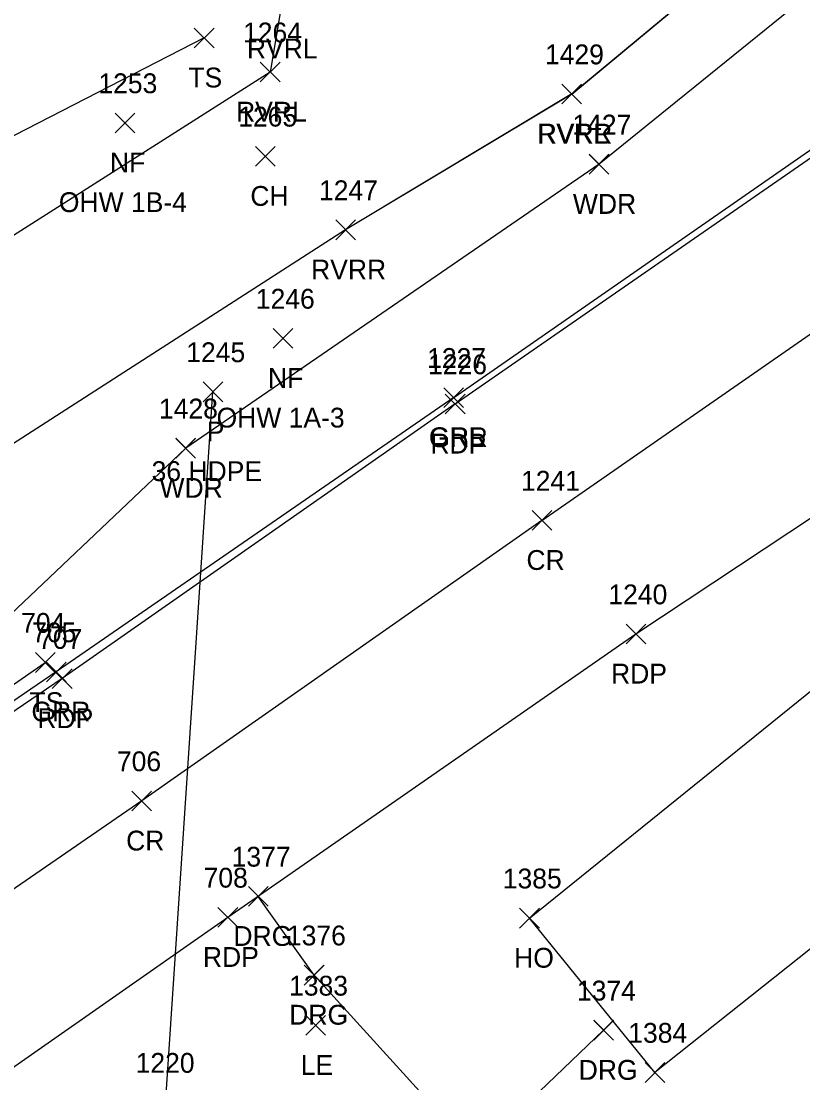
# Model space of a CAD drawing. Extents: x 1528286 to 1556263, y 492387 to 508952.
# Drawn here: x 1528937.9 to 1529016.8, y 492961.3 to 493068.5 of the extents above; entities that cross this region are included whole.
import ezdxf

# ---------------------------------------------------------------- set-up
doc = ezdxf.new("R2010")
doc.units = 0
for name, color, linetype in [('D_A', 7, 'Continuous'), ('D_C', 7, 'Continuous'), ('D_I', 7, 'Continuous'), ('D_TIC', 7, 'Continuous'), ('DCP', 7, 'Continuous'), ('L_A', 7, 'Continuous'), ('L_C', 7, 'Continuous'), ('L_I', 7, 'Continuous'), ('L_TIC', 7, 'Continuous'), ('LAWA', 7, 'Continuous'), ('LAWE', 7, 'Continuous'), ('LBC', 7, 'Continuous'), ('LELB', 7, 'Continuous'), ('P_A', 7, 'Continuous'), ('P_I', 7, 'Continuous'), ('P_TIC', 7, 'Continuous'), ('PET', 7, 'Continuous'), ('PRC', 7, 'Continuous'), ('R_A', 7, 'Continuous'), ('R_I', 7, 'Continuous'), ('R_TIC', 7, 'Continuous'), ('RDG', 7, 'Continuous'), ('RGR', 7, 'Continuous')]:
    doc.layers.add(name, color=color, linetype=linetype)

msp = doc.modelspace()

# ---------------------------------------------------------------- linework, layer by layer
at = {"layer": 'D_TIC'}
for points in [[(1528956.21, 493030.06), (1528958.21, 493032.06)], [(1528958.21, 493030.06), (1528956.21, 493032.06)], [(1528956.21, 493030.06), (1528958.21, 493032.06)], [(1528958.21, 493030.06), (1528956.21, 493032.06)]]:
    msp.add_lwpolyline(points, dxfattribs=at)
at = {"layer": 'DCP'}
msp.add_lwpolyline([(1528951.98, 492952.57), (1528957.21, 493031.06)], dxfattribs=at)
msp.add_lwpolyline([(1528951.98, 492952.57), (1528957.21, 493031.06)], dxfattribs=at)
at = {"layer": 'L_TIC'}
for points in [[(1528955.32, 493065.79), (1528957.32, 493067.79)], [(1528957.32, 493065.79), (1528955.32, 493067.79)], [(1528955.32, 493065.79), (1528957.32, 493067.79)], [(1528957.32, 493065.79), (1528955.32, 493067.79)], [(1528961.99, 493062.34), (1528963.99, 493064.34)], [(1528963.99, 493062.34), (1528961.99, 493064.34)], [(1528961.99, 493062.34), (1528963.99, 493064.34)], [(1528963.99, 493062.34), (1528961.99, 493064.34)], [(1528992.43, 493060.13), (1528994.43, 493062.13)], [(1528994.43, 493060.13), (1528992.43, 493062.13)], [(1528992.43, 493060.13), (1528994.43, 493062.13)], [(1528994.43, 493060.13), (1528992.43, 493062.13)], [(1528992.43, 493060.12), (1528994.43, 493062.12)], [(1528994.43, 493060.12), (1528992.43, 493062.12)], [(1528992.43, 493060.12), (1528994.43, 493062.12)], [(1528994.43, 493060.12), (1528992.43, 493062.12)], [(1528947.34, 493057.21), (1528949.34, 493059.21)], [(1528949.34, 493057.21), (1528947.34, 493059.21)], [(1528947.34, 493057.21), (1528949.34, 493059.21)], [(1528949.34, 493057.21), (1528947.34, 493059.21)], [(1528961.5, 493053.84), (1528963.5, 493055.84)], [(1528963.5, 493053.84), (1528961.5, 493055.84)], [(1528961.5, 493053.84), (1528963.5, 493055.84)], [(1528963.5, 493053.84), (1528961.5, 493055.84)], [(1528995.19, 493053.04), (1528997.19, 493055.04)], [(1528997.19, 493053.04), (1528995.19, 493055.04)], [(1528995.19, 493053.03), (1528997.19, 493055.03)], [(1528997.19, 493053.03), (1528995.19, 493055.03)], [(1528969.61, 493046.41), (1528971.61, 493048.41)], [(1528971.61, 493046.41), (1528969.61, 493048.41)], [(1528969.61, 493046.41), (1528971.61, 493048.41)], [(1528971.61, 493046.41), (1528969.61, 493048.41)], [(1528963.29, 493035.46), (1528965.29, 493037.46)], [(1528965.29, 493035.46), (1528963.29, 493037.46)], [(1528963.29, 493035.46), (1528965.29, 493037.46)], [(1528965.29, 493035.46), (1528963.29, 493037.46)], [(1528953.46, 493024.38), (1528955.46, 493026.38)], [(1528955.46, 493024.38), (1528953.46, 493026.38)], [(1528953.46, 493024.37), (1528955.46, 493026.37)], [(1528955.46, 493024.37), (1528953.46, 493026.37)], [(1528939.29, 493002.74), (1528941.29, 493004.74)], [(1528941.29, 493002.74), (1528939.29, 493004.74)], [(1528939.29, 493002.74), (1528941.29, 493004.74)], [(1528941.29, 493002.74), (1528939.29, 493004.74)], [(1528988.17, 492976.94), (1528990.17, 492978.94)], [(1528990.17, 492976.94), (1528988.17, 492978.94)], [(1528988.17, 492976.94), (1528990.17, 492978.94)], [(1528990.17, 492976.94), (1528988.17, 492978.94)], [(1528966.59, 492966.12), (1528968.59, 492968.12)], [(1528968.59, 492966.12), (1528966.59, 492968.12)], [(1528966.59, 492966.12), (1528968.59, 492968.12)], [(1528968.59, 492966.12), (1528966.59, 492968.12)], [(1529000.83, 492961.36), (1529002.83, 492963.36)], [(1529002.83, 492961.36), (1529000.83, 492963.36)], [(1529000.83, 492961.36), (1529002.83, 492963.36)], [(1529002.83, 492961.36), (1529000.83, 492963.36)]]:
    msp.add_lwpolyline(points, dxfattribs=at)
at = {"layer": 'LAWA'}
for points in [[(1529161.79, 493169.98), (1529145.79, 493161.64), (1529103.54, 493137.09), (1529078.89, 493120.12), (1529036.96, 493087.03), (1528996.19, 493054.04), (1528954.46, 493025.37)], [(1529161.79, 493169.98), (1529145.79, 493161.64), (1529103.54, 493137.09), (1529078.89, 493120.12), (1529036.96, 493087.03), (1528996.19, 493054.03), (1528954.46, 493025.38)], [(1528954.46, 493025.38), (1528932.82, 493004.86)], [(1528954.46, 493025.37), (1528932.82, 493004.86)]]:
    msp.add_lwpolyline(points, dxfattribs=at)
at = {"layer": 'LAWE'}
for points in [[(1528993.43, 493061.12), (1529028.67, 493090.37), (1529051.82, 493126.54), (1529095.12, 493164.29)], [(1528993.43, 493061.13), (1529028.67, 493090.37), (1529051.83, 493126.54), (1529095.12, 493164.29)], [(1528964.08, 493069.72), (1528962.99, 493063.34)], [(1528964.07, 493069.72), (1528962.99, 493063.34)], [(1528962.99, 493063.34), (1528890.67, 493017.33), (1528875.74, 493008.39), (1528841.38, 492996.85), (1528822.77, 492990.39)], [(1528962.99, 493063.34), (1528890.67, 493017.33), (1528875.74, 493008.39), (1528841.38, 492996.85), (1528822.77, 492990.39)], [(1528993.43, 493061.13), (1528970.61, 493047.41)], [(1528993.43, 493061.12), (1528970.61, 493047.41)], [(1528970.61, 493047.41), (1528902.86, 493003.86), (1528888.6, 492991.51), (1528860.16, 492972.68)], [(1528970.61, 493047.41), (1528902.86, 493003.86), (1528888.6, 492991.51), (1528860.16, 492972.68)]]:
    msp.add_lwpolyline(points, dxfattribs=at)
at = {"layer": 'LBC'}
msp.add_lwpolyline([(1529001.83, 492962.36), (1528989.17, 492977.94), (1529034.67, 493014.69), (1529047.99, 492999.03), (1529001.83, 492962.36)], dxfattribs=at)
msp.add_lwpolyline([(1529001.83, 492962.36), (1528989.17, 492977.94), (1529034.67, 493014.69), (1529047.99, 492999.03), (1529001.83, 492962.36)], dxfattribs=at)
at = {"layer": 'LELB'}
for points in [[(1528956.32, 493066.79), (1528901.19, 493038.46), (1528892.87, 493033.69), (1528869.88, 493022.89)], [(1528956.32, 493066.79), (1528901.19, 493038.46), (1528892.87, 493033.69), (1528869.88, 493022.89)], [(1528511.53, 492702.85), (1528534.14, 492721.31), (1528572.64, 492751.16), (1528586.73, 492763.59), (1528600.5, 492766.35), (1528613.46, 492775.52), (1528652.2, 492802.53), (1528688.62, 492828.26), (1528710.29, 492843.12), (1528742.91, 492866.47), (1528778.71, 492891.27), (1528817.45, 492919.08), (1528857.75, 492946.94), (1528897.37, 492973.98), (1528940.29, 493003.74)], [(1528511.53, 492702.85), (1528534.14, 492721.31), (1528572.64, 492751.16), (1528586.73, 492763.59), (1528600.5, 492766.35), (1528613.46, 492775.52), (1528652.2, 492802.53), (1528688.62, 492828.26), (1528710.29, 492843.12), (1528742.91, 492866.47), (1528778.71, 492891.27), (1528817.45, 492919.08), (1528857.75, 492946.94), (1528897.37, 492973.98), (1528940.29, 493003.74)]]:
    msp.add_lwpolyline(points, dxfattribs=at)
at = {"layer": 'P_TIC'}
for points in [[(1528980.67, 493028.84), (1528982.67, 493030.84)], [(1528982.67, 493028.84), (1528980.67, 493030.84)], [(1528980.67, 493028.84), (1528982.67, 493030.84)], [(1528982.67, 493028.84), (1528980.67, 493030.84)], [(1528989.43, 493017.09), (1528991.43, 493019.09)], [(1528991.43, 493017.09), (1528989.43, 493019.09)], [(1528989.43, 493017.09), (1528991.43, 493019.09)], [(1528991.43, 493017.09), (1528989.43, 493019.09)], [(1528998.91, 493005.62), (1529000.91, 493007.62)], [(1529000.91, 493005.62), (1528998.91, 493007.62)], [(1528998.91, 493005.62), (1529000.91, 493007.62)], [(1529000.91, 493005.62), (1528998.91, 493007.62)], [(1528941, 493001.12), (1528943, 493003.12)], [(1528943, 493001.12), (1528941, 493003.12)], [(1528941, 493001.12), (1528943, 493003.12)], [(1528943, 493001.12), (1528941, 493003.12)], [(1528949.02, 492988.77), (1528951.02, 492990.77)], [(1528951.02, 492988.77), (1528949.02, 492990.77)], [(1528949.02, 492988.77), (1528951.02, 492990.77)], [(1528951.02, 492988.77), (1528949.02, 492990.77)], [(1528957.71, 492977.02), (1528959.71, 492979.02)], [(1528959.71, 492977.02), (1528957.71, 492979.02)], [(1528957.71, 492977.02), (1528959.71, 492979.02)], [(1528959.71, 492977.02), (1528957.71, 492979.02)]]:
    msp.add_lwpolyline(points, dxfattribs=at)
at = {"layer": 'PET'}
for points in [[(1528981.67, 493029.84), (1529023.32, 493058.68), (1529062.76, 493086.59), (1529101.46, 493113.53), (1529137.06, 493138.01), (1529145.3, 493125.26), (1529153.7, 493113.65), (1529119.46, 493089.42), (1529079.43, 493062), (1529041.27, 493034), (1528999.91, 493006.62)], [(1528981.67, 493029.84), (1529023.32, 493058.68), (1529062.76, 493086.59), (1529101.46, 493113.53), (1529137.06, 493138.01), (1529145.3, 493125.26), (1529153.7, 493113.65), (1529119.46, 493089.42), (1529079.43, 493062), (1529041.27, 493034), (1528999.91, 493006.62)], [(1528981.67, 493029.84), (1528942, 493002.12)], [(1528981.67, 493029.84), (1528942, 493002.12)], [(1528999.91, 493006.62), (1528958.71, 492978.02)], [(1528999.91, 493006.62), (1528958.71, 492978.02)], [(1528942, 493002.12), (1528898.48, 492972.51), (1528859.28, 492945.34), (1528819.08, 492917.53), (1528787.55, 492894.48), (1528780.46, 492889.94), (1528744.23, 492865.12), (1528711.17, 492841.82), (1528689.56, 492826.66), (1528653.33, 492801.52)], [(1528942, 493002.12), (1528898.48, 492972.51), (1528859.28, 492945.34), (1528819.08, 492917.53), (1528787.55, 492894.48), (1528780.46, 492889.94), (1528744.23, 492865.12), (1528711.17, 492841.82), (1528689.56, 492826.66), (1528653.33, 492801.52)], [(1528958.71, 492978.02), (1528915.24, 492947.63), (1528876.05, 492920.66), (1528835.6, 492893.02)], [(1528958.71, 492978.02), (1528915.24, 492947.63), (1528876.05, 492920.66), (1528835.6, 492893.02)]]:
    msp.add_lwpolyline(points, dxfattribs=at)
at = {"layer": 'PRC'}
for points in [[(1528990.43, 493018.09), (1529032.37, 493047.2), (1529072.04, 493074.3), (1529110.99, 493101.46)], [(1528990.43, 493018.09), (1529032.37, 493047.2), (1529072.04, 493074.3), (1529110.99, 493101.46)], [(1528990.43, 493018.09), (1528950.02, 492989.77)], [(1528990.43, 493018.09), (1528950.02, 492989.77)], [(1528950.02, 492989.77), (1528907.21, 492960.29), (1528867.74, 492932.71), (1528827.79, 492905.43)], [(1528950.02, 492989.77), (1528907.21, 492960.29), (1528867.74, 492932.71), (1528827.79, 492905.43)]]:
    msp.add_lwpolyline(points, dxfattribs=at)
at = {"layer": 'R_TIC'}
for points in [[(1528980.52, 493029.48), (1528982.52, 493031.48)], [(1528982.52, 493029.48), (1528980.52, 493031.48)], [(1528980.52, 493029.48), (1528982.52, 493031.48)], [(1528982.52, 493029.48), (1528980.52, 493031.48)], [(1528980.52, 493029.48), (1528982.52, 493031.48)], [(1528982.52, 493029.48), (1528980.52, 493031.48)], [(1528980.52, 493029.48), (1528982.52, 493031.48)], [(1528982.52, 493029.48), (1528980.52, 493031.48)], [(1528940.4, 493001.79), (1528942.4, 493003.79)], [(1528942.4, 493001.79), (1528940.4, 493003.79)], [(1528940.4, 493001.79), (1528942.4, 493003.79)], [(1528942.4, 493001.79), (1528940.4, 493003.79)], [(1528960.79, 492979.14), (1528962.79, 492981.14)], [(1528962.79, 492979.14), (1528960.79, 492981.14)], [(1528960.79, 492979.14), (1528962.79, 492981.14)], [(1528962.79, 492979.14), (1528960.79, 492981.14)], [(1528966.42, 492971.19), (1528968.42, 492973.19)], [(1528968.42, 492971.19), (1528966.42, 492973.19)], [(1528966.43, 492971.19), (1528968.43, 492973.19)], [(1528968.43, 492971.19), (1528966.43, 492973.19)], [(1528995.65, 492965.63), (1528997.65, 492967.63)], [(1528997.65, 492965.63), (1528995.65, 492967.63)], [(1528995.65, 492965.62), (1528997.65, 492967.62)], [(1528997.65, 492965.62), (1528995.65, 492967.62)]]:
    msp.add_lwpolyline(points, dxfattribs=at)
at = {"layer": 'RDG'}
for points in [[(1528996.65, 492966.62), (1528983.73, 492954.24), (1528967.43, 492972.19), (1528961.79, 492980.14)], [(1528996.65, 492966.63), (1528983.73, 492954.25), (1528967.42, 492972.19), (1528961.79, 492980.14)]]:
    msp.add_lwpolyline(points, dxfattribs=at)
at = {"layer": 'RGR'}
for points in [[(1528981.52, 493030.48), (1529023.06, 493059.33), (1529062.66, 493086.9), (1529100.29, 493115.36)], [(1528981.52, 493030.48), (1529023.06, 493059.33), (1529062.66, 493086.9), (1529100.29, 493115.36)], [(1528981.52, 493030.48), (1528941.4, 493002.79)], [(1528981.52, 493030.48), (1528941.4, 493002.79)], [(1528941.4, 493002.79), (1528898.12, 492973.22), (1528858.97, 492945.9), (1528818.83, 492918.12), (1528780.05, 492890.64), (1528744.15, 492865.31), (1528711.24, 492842.07), (1528689.6, 492826.87), (1528653.3, 492801.62)], [(1528941.4, 493002.79), (1528898.12, 492973.22), (1528858.97, 492945.9), (1528818.83, 492918.12), (1528780.05, 492890.64), (1528744.15, 492865.31), (1528711.24, 492842.07), (1528689.6, 492826.87), (1528653.3, 492801.62)]]:
    msp.add_lwpolyline(points, dxfattribs=at)

# ---------------------------------------------------------------- texts
at = {"layer": 'D_A'}
msp.add_text('P', height=2, dxfattribs=at).set_placement((1528956.59, 493026.06))
msp.add_text('P', height=2, dxfattribs=at).set_placement((1528956.59, 493026.06))
at = {"layer": 'D_C'}
msp.add_text('36 HDPE', height=2, dxfattribs=at).set_placement((1528951.02, 493022.06))
msp.add_text('36 HDPE', height=2, dxfattribs=at).set_placement((1528951.02, 493022.06))
at = {"layer": 'D_I'}
msp.add_text('1245', height=2, dxfattribs=at).set_placement((1528954.52, 493034.06))
msp.add_text('1245', height=2, dxfattribs=at).set_placement((1528954.52, 493034.06))
at = {"layer": 'L_A'}
for s, p in [('RVRL', (1528960.64, 493064.72)), ('RVRL', (1528960.64, 493064.72)), ('TS', (1528954.73, 493061.79)), ('TS', (1528954.73, 493061.79)), ('RVRL', (1528959.55, 493058.34)), ('RVRL', (1528959.55, 493058.34)), ('RVRR', (1528989.94, 493056.13)), ('RVRR', (1528989.94, 493056.12)), ('RVRL', (1528989.99, 493056.12)), ('RVRL', (1528990, 493056.13)), ('NF', (1528946.82, 493053.21)), ('NF', (1528946.82, 493053.21)), ('CH', (1528960.99, 493049.84)), ('CH', (1528960.99, 493049.84)), ('WDR', (1528993.55, 493049.04)), ('WDR', (1528993.55, 493049.03)), ('RVRR', (1528967.12, 493042.41)), ('RVRR', (1528967.12, 493042.41)), ('NF', (1528962.77, 493031.46)), ('NF', (1528962.77, 493031.46)), ('WDR', (1528951.82, 493020.38)), ('WDR', (1528951.82, 493020.37)), ('TS', (1528938.7, 492998.74)), ('TS', (1528938.7, 492998.74)), ('HO', (1528987.62, 492972.94)), ('HO', (1528987.62, 492972.94)), ('LE', (1528966.08, 492962.12)), ('LE', (1528966.08, 492962.12))]:
    msp.add_text(s, height=2, dxfattribs=at).set_placement(p)
at = {"layer": 'L_C'}
for s, p in [('OHW 1B-4', (1528941.66, 493049.21)), ('OHW 1B-4', (1528941.66, 493049.21)), ('OHW 1A-3', (1528957.58, 493027.46)), ('OHW 1A-3', (1528957.58, 493027.46))]:
    msp.add_text(s, height=2, dxfattribs=at).set_placement(p)
at = {"layer": 'L_I'}
for s, p in [('1264', (1528960.25, 493066.34)), ('1264', (1528960.25, 493066.34)), ('1429', (1528990.73, 493064.13)), ('1429', (1528990.73, 493064.13)), ('1429', (1528990.73, 493064.12)), ('1429', (1528990.73, 493064.12)), ('1253', (1528945.65, 493061.21)), ('1253', (1528945.65, 493061.21)), ('1265', (1528959.76, 493057.84)), ('1265', (1528959.76, 493057.84)), ('1427', (1528993.5, 493057.04)), ('1427', (1528993.49, 493057.03)), ('1247', (1528967.92, 493050.41)), ('1247', (1528967.92, 493050.41)), ('1246', (1528961.54, 493039.46)), ('1246', (1528961.54, 493039.46)), ('1428', (1528951.77, 493028.38)), ('1428', (1528951.76, 493028.37)), ('704', (1528937.85, 493006.74)), ('704', (1528937.85, 493006.74)), ('1385', (1528986.47, 492980.94)), ('1385', (1528986.47, 492980.94)), ('1383', (1528964.9, 492970.12)), ('1383', (1528964.9, 492970.12)), ('1384', (1528999.14, 492965.36)), ('1384', (1528999.14, 492965.36)), ('1220', (1528949.41, 492962.33)), ('1220', (1528949.41, 492962.33))]:
    msp.add_text(s, height=2, dxfattribs=at).set_placement(p)
at = {"layer": 'P_A'}
for s, p in [('RDP', (1528979.16, 493024.84)), ('RDP', (1528979.16, 493024.84)), ('CR', (1528988.86, 493013.09)), ('CR', (1528988.86, 493013.09)), ('RDP', (1528997.4, 493001.62)), ('RDP', (1528997.4, 493001.62)), ('RDP', (1528939.49, 492997.12)), ('RDP', (1528939.49, 492997.12)), ('CR', (1528948.45, 492984.77)), ('CR', (1528948.45, 492984.77)), ('RDP', (1528956.2, 492973.02)), ('RDP', (1528956.2, 492973.02))]:
    msp.add_text(s, height=2, dxfattribs=at).set_placement(p)
at = {"layer": 'P_I'}
for s, p in [('1226', (1528978.93, 493032.84)), ('1226', (1528978.93, 493032.84)), ('1241', (1528988.31, 493021.09)), ('1241', (1528988.31, 493021.09)), ('1240', (1528997.13, 493009.62)), ('1240', (1528997.13, 493009.62)), ('707', (1528939.56, 493005.12)), ('707', (1528939.56, 493005.12)), ('706', (1528947.52, 492992.77)), ('706', (1528947.52, 492992.77)), ('708', (1528956.27, 492981.02)), ('708', (1528956.27, 492981.02))]:
    msp.add_text(s, height=2, dxfattribs=at).set_placement(p)
at = {"layer": 'R_A'}
for s, p in [('GRR', (1528979.01, 493025.48)), ('GRR', (1528979.01, 493025.48)), ('GRL', (1528979.06, 493025.48)), ('GRL', (1528979.06, 493025.48)), ('GRR', (1528938.89, 492997.79)), ('GRR', (1528938.89, 492997.79)), ('DRG', (1528959.28, 492975.14)), ('DRG', (1528959.28, 492975.14)), ('DRG', (1528964.91, 492967.19)), ('DRG', (1528964.92, 492967.19)), ('DRG', (1528994.13, 492961.63)), ('DRG', (1528994.14, 492961.62))]:
    msp.add_text(s, height=2, dxfattribs=at).set_placement(p)
at = {"layer": 'R_I'}
for s, p in [('1227', (1528978.83, 493033.48)), ('1227', (1528978.83, 493033.48)), ('1227', (1528978.83, 493033.48)), ('1227', (1528978.83, 493033.48)), ('705', (1528938.96, 493005.79)), ('705', (1528938.96, 493005.79)), ('1377', (1528959.1, 492983.14)), ('1377', (1528959.1, 492983.14)), ('1376', (1528964.68, 492975.19)), ('1376', (1528964.68, 492975.19)), ('1374', (1528993.96, 492969.62)), ('1374', (1528993.95, 492969.63))]:
    msp.add_text(s, height=2, dxfattribs=at).set_placement(p)

doc.saveas('drawing.dxf')
